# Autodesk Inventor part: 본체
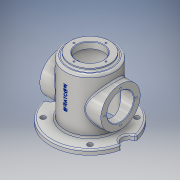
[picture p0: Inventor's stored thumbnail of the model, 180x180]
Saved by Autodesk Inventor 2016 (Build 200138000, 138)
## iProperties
Created: 2018-04
Part Number: 본체
Material: 알루미늄 6061
Document SubType Name: Modeling
Designer: 605-07
Density: 2.7 g/cm^3
Appearance: 알루미늄 - 평지
Mass: 1148.04 g
Surface Area: 1202.83 cm^2
Volume: 425.198 cm^3
Author: 605-07
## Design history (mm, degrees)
sketch "스케치1"
  geometry: A1 r 15 centre (80, 0) between (78.594, 14.934) and (78.594, -14.934); A2 r 15 centre (-80, 0) between (-78.594, -14.934) and (-78.594, 14.934); A3 r 80 centre (0, 0) between (78.594, 14.934) and (-78.594, 14.934); A4 r 80 centre (0, 0) between (-78.594, -14.934) and (78.594, -14.934); 1 further point
  constraints: 8 point on circle, 4 centre point, 1 coincident
  dimensions: "d1" = 30 diameter of A1; "d2" = 30 diameter of A2
extrude "돌출1" new body sketch "스케치1" distance "d3" = 10; taper "d4" = 0 deg
sketch "스케치2"
  geometry: C1 r 50 at (0, 0); 1 further point
  constraints: 1 centre point, 1 coincident
  dimensions: "d6" = 100 diameter of C1
extrude "돌출2" join sketch "스케치2" distance "d7" = 110; taper "d8" = 0 deg
sketch "스케치3"
  geometry: C1 r 40 at (0, 0); 1 further point
  constraints: 1 centre point, 1 coincident
  dimensions: "d9" = 80 diameter of C1
extrude "돌출3" join sketch "스케치3" distance "d10" = 5; taper "d11" = 0 deg
sketch "스케치4"
  geometry: C1 r 50 at (0, 0); 1 further point
  constraints: 1 centre point, 1 coincident
  dimensions: "d12" = 100 diameter of C1
extrude "돌출4" join sketch "스케치4" distance "d13" = 8; taper "d14" = 0 deg
sketch "스케치5"
  geometry: L1 (0, 0)-(60, 0); C1 r 40 at (60, 0)
  constraints: 2 end point, 1 centre point, 1 coincident, 1 horizontal
  dimensions: "d15" = 60 distance of L1.start L1.end; "d16" = 80 diameter of C1
extrude "돌출5" join sketch "스케치5" stored distance "d17" = 124; taper "d18" = 0 deg
sketch "스케치6"
  geometry: C1 r 45 at (0, 0); 1 further point
  constraints: 1 centre point, 1 coincident
  dimensions: "d19" = 90 diameter of C1
extrude "돌출6" cut sketch "스케치6" distance "d20" = 120; taper "d21" = 0 deg
sketch "스케치7"
  geometry: C1 r 27 at (0, 0); 1 further point
  constraints: 1 centre point
  dimensions: "d22" = 54 diameter of C1
extrude "돌출7" cut sketch "스케치7" stored distance "d23" = 120; taper "d24" = 0 deg
sketch "스케치8" dims "d25" = 65
  geometry: C1 r 40 at (0, 0) reference; 3 further points
  constraints: 1 coincident, 1 vertical alignment, 2 other
hole "구멍1" sketch "스케치8" at (0, -32.5) diameter "d26" = 3.242; stored, may be unused: countersink angle "d30" = 90 deg, drill point angle "d32" = 118 deg; dims "d27" = 8, "d28" = 4, "d29" = 2, "d31" = 10
sketch "스케치9" dims "d36" = 135
  geometry: L1 (0, 0)-(70.811, 70.811); L2 (0, 0)-(100.142, 0); C1 r 45 at (0, 0) reference; 3 further points
  constraints: 4 end point, 1 coincident, 1 equal length, 1 horizontal, 1 point on line, 3 other
  dimensions: "d37" = 45 deg angle of L2 L1
hole "구멍2" sketch "스케치9" at (47.73, 47.73) diameter "d38" = 10; stored, may be unused: countersink angle "d42" = 90 deg, drill point angle "d44" = 118 deg; dims "d39" = 8, "d40" = 4, "d41" = 2, "d43" = 20
sketch "스케치10"
  geometry: C1 r 27 at (0, 0); 1 further point
  constraints: 1 centre point, 1 coincident
  dimensions: "d48" = 54 diameter of C1
extrude "돌출8" cut sketch "스케치10" distance "d49" = 120; taper "d50" = 0 deg
sketch "스케치11" dims "d51" = 65
  geometry: 3 further points
  constraints: 1 coincident, 1 horizontal alignment, 2 other
hole "구멍3" sketch "스케치11" at (-32.5, 0) diameter "d52" = 3.242; stored, may be unused: countersink angle "d56" = 90 deg, drill point angle "d58" = 118 deg; dims "d53" = 8, "d54" = 4, "d55" = 2, "d57" = 10
fillet "모깎기1" dims "d62" = 5
fillet "모깎기2" dims "d63" = 3
node "작업 평면1"
sketch "스케치12"
  geometry: L1 (0, -10)-(0, 60); L2 (-30.158, 48.62)-(-30.158, 71.38); L3 (-30.158, 71.38)-(30.158, 71.38); L4 (30.158, 71.38)-(30.158, 48.62); L5 (30.158, 48.62)-(-30.158, 48.62); 2 further points
  constraints: 2 end point, 2 midpoint, 1 horizontal alignment, 1 vertical, 1 vertical alignment, 2 other
  dimensions: "d67" = 70 distance of L1.start L1.end
feature "엠보싱1" sketch "스케치12" dims "d1" = 30, "d2" = 30, "d68" = 0.5, "d69" = 0
chamfer "모따기2" distance "d70" = 1; stored, may be unused: second distance "d71" = 2, angle "d72" = 45 deg
node "솔리드1"
pattern_circular "원형 패턴1" dims angle "d34" = 360 deg
mirror "대칭1"
pattern_circular "원형 패턴2" dims angle "d46" = 360 deg
pattern_circular "원형 패턴3" dims angle "d60" = 360 deg
